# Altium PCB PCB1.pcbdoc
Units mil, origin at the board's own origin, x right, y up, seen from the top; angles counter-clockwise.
Board outline 1725 x 1680 mil, 2 copper layers (Top Layer, Bottom Layer); 21 components, 21 nets, 83 pads, 18 vias.
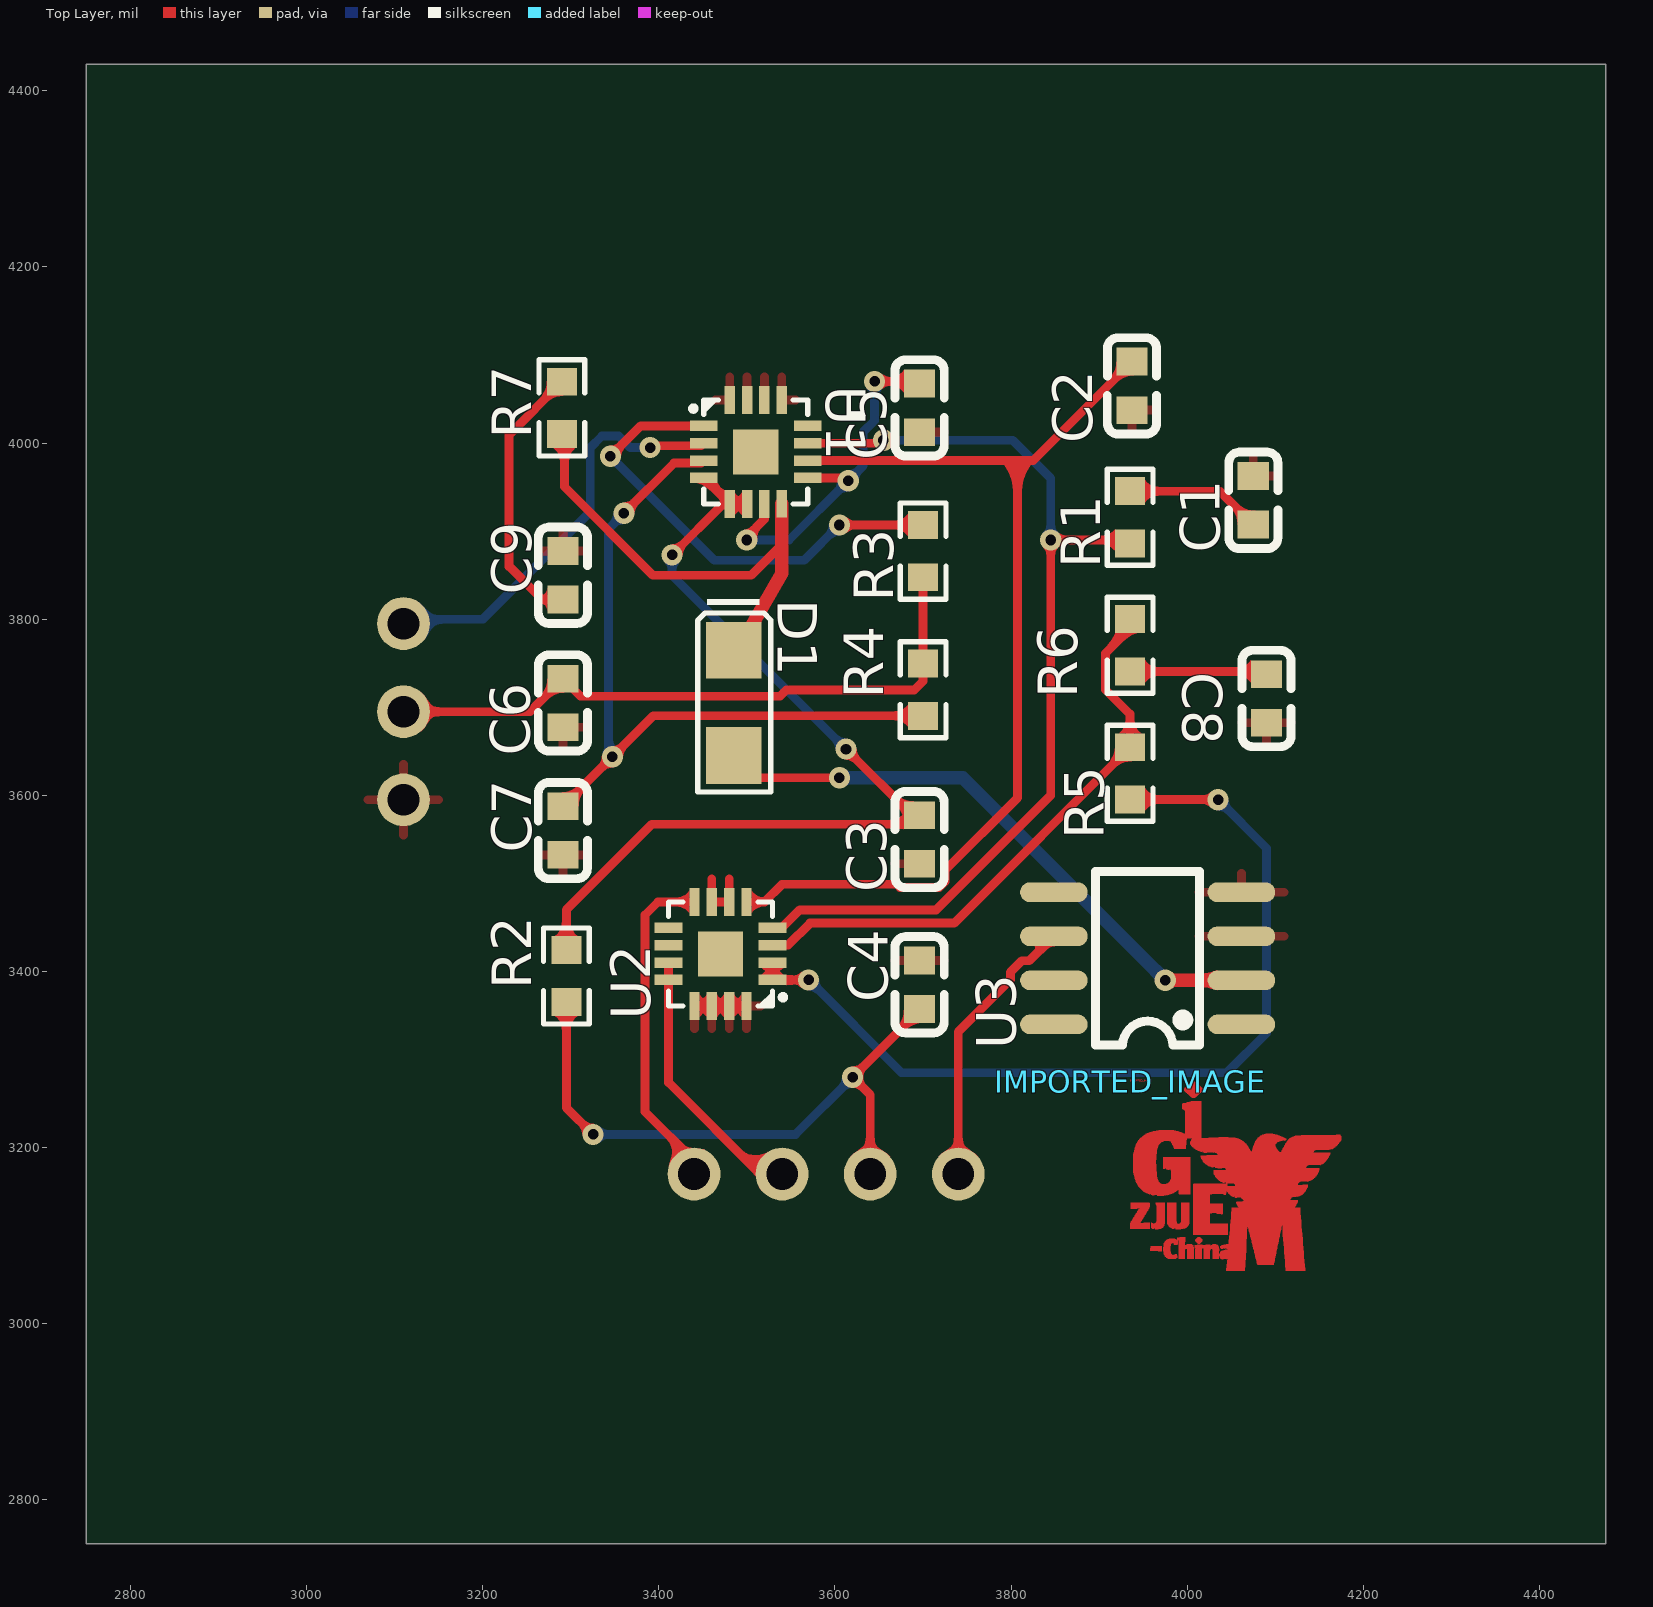
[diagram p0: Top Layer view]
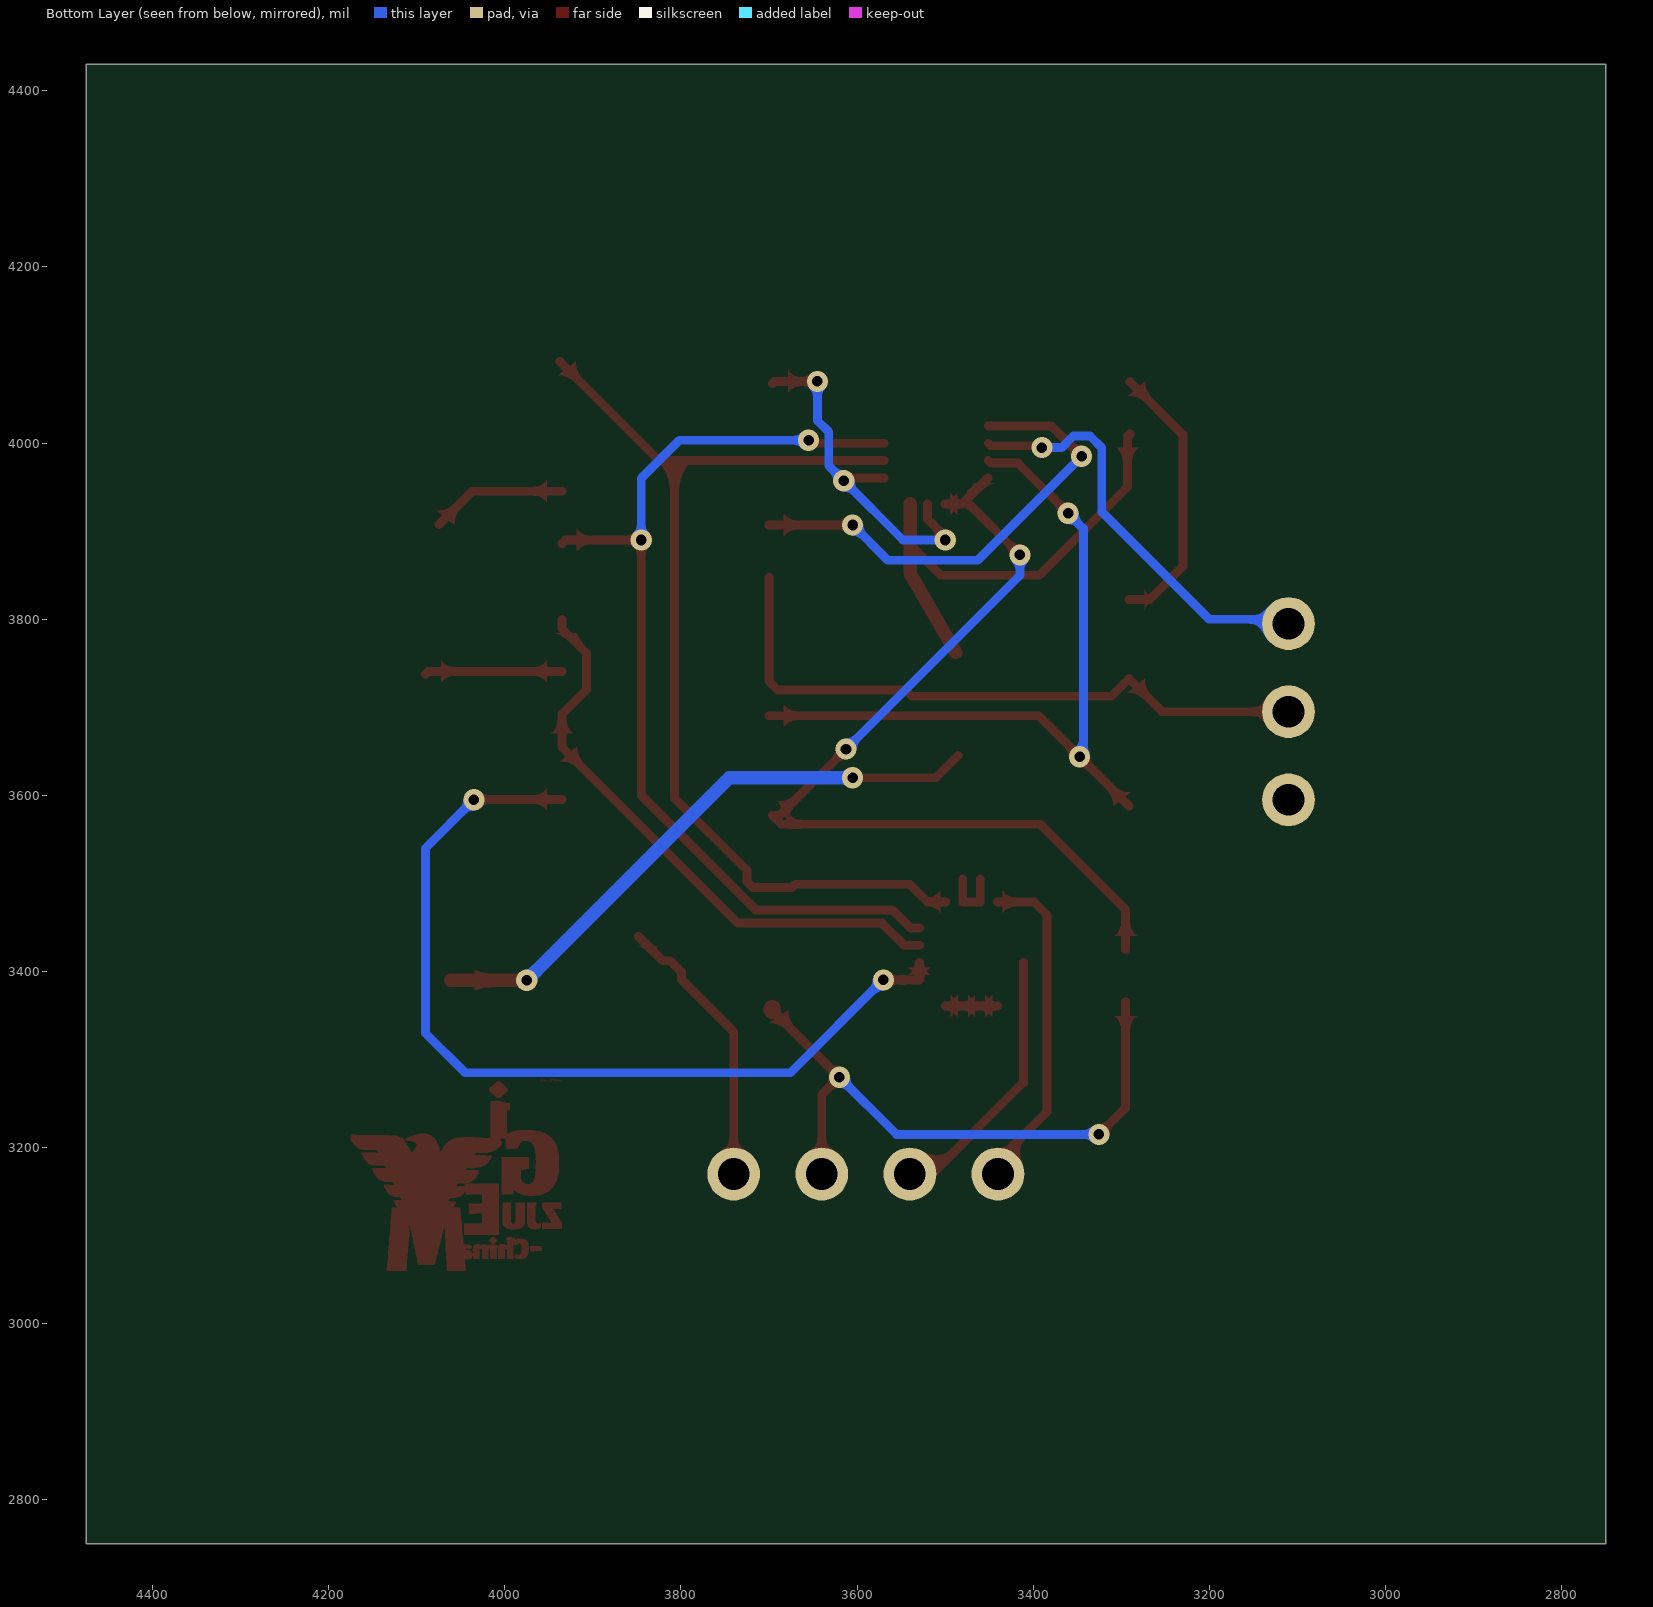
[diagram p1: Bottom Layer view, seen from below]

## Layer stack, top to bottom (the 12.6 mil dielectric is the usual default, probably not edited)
Top Layer: signal copper (thickness not stored)
Dielectric: dielectric 12.6, FR-4, Dk 4.8
Bottom Layer: signal copper (thickness not stored)

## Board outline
4475,2750 2750,2750 2750,4430 4475,4430

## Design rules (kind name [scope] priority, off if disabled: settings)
BoardOutlineClearance copperThickness1oz [All] p0: genericclearance=10 ignorepadtopadclearanceinfootprint=FALSE except(0: Arc-SplitContinuation Track-SplitContinuation SMDPad-SplitContinuation THPad-SplitContinuation Via-SplitContinuation Fill-SplitContinuation Poly-SplitContinuation Region-SplitContinuation Text-SplitContinuation; 6: Track-CutoutEdge SMDPad-CutoutEdge THPad-CutoutEdge Via-CutoutEdge Region-CutoutEdge; 11.8: Track-OutlineEdge SMDPad-OutlineEdge THPad-OutlineEdge Via-OutlineEdge Fill-OutlineEdge Region-OutlineEdge Poly-OutlineEdge Text-OutlineEdge Fill-CutoutEdge)
BoardOutlineClearance copperThickness2oz [All] p0: genericclearance=10 ignorepadtopadclearanceinfootprint=FALSE except(0: Arc-SplitContinuation Track-SplitContinuation SMDPad-SplitContinuation THPad-SplitContinuation Via-SplitContinuation Fill-SplitContinuation Poly-SplitContinuation Region-SplitContinuation Text-SplitContinuation; 6: Track-CutoutEdge SMDPad-CutoutEdge THPad-CutoutEdge Via-CutoutEdge Region-CutoutEdge; 11.8: Track-OutlineEdge SMDPad-OutlineEdge THPad-OutlineEdge Via-OutlineEdge Fill-OutlineEdge Region-OutlineEdge Poly-OutlineEdge Text-OutlineEdge Fill-CutoutEdge)
Clearance copperThickness1oz [(InNet('GND') OR InNet('$1N480') OR InNet('$1N501') OR InNet('$1N735') OR InNet('VP_HIGH') OR InNet('$1N663') OR InNet('VP_LOW') OR InNet('$1N1053') OR InNet('$1N1472') OR InNet('$1N1627') OR InNet('$1N1759') OR InNet('$1N2068') OR InNet('$1N382') OR InNet('$1N996') OR InNet('$1N1333') OR InNet('$1N1394') OR InNet('VSET') OR InNet('OUTPUT') OR InNet('3V_TO_12V') OR InNet('+5V') OR InNet('DATA_PATH'))] p1: gap=7 ignorepadtopadclearanceinfootprint=FALSE except(4: Track-Track; 6: Track-SMDPad SMDPad-SMDPad Track-THPad SMDPad-THPad THPad-THPad Track-Via SMDPad-Via THPad-Via Via-Via SMDPad-Fill THPad-Fill Via-Fill Fill-Fill Track-Region SMDPad-Region THPad-Region Via-Region Region-Region Track-Poly SMDPad-Poly THPad-Poly Via-Poly Fill-Poly Region-Poly Poly-Poly Track-Text SMDPad-Text THPad-Text Via-Text Fill-Text Region-Text Poly-Text Text-Text; 6.9: Track-Hole SMDPad-Hole THPad-Hole Via-Hole Fill-Hole Region-Hole Poly-Hole Text-Hole Sheet-Hole; 11.8: Track-Fill Fill-Region Track-Sheet SMDPad-Sheet THPad-Sheet Via-Sheet Fill-Sheet Region-Sheet Poly-Sheet Text-Sheet)
Clearance copperThickness2oz [All] p1: gap=7 ignorepadtopadclearanceinfootprint=FALSE except(6: Track-SMDPad SMDPad-SMDPad Track-THPad SMDPad-THPad THPad-THPad Track-Via SMDPad-Via THPad-Via Via-Via SMDPad-Fill THPad-Fill Via-Fill Fill-Fill Track-Region SMDPad-Region THPad-Region Via-Region Region-Region Track-Poly SMDPad-Poly THPad-Poly Via-Poly Fill-Poly Region-Poly Poly-Poly Track-Text SMDPad-Text THPad-Text Via-Text Fill-Text Region-Text Poly-Text Text-Text; 6.9: Track-Hole SMDPad-Hole THPad-Hole Via-Hole Fill-Hole Region-Hole Poly-Hole Text-Hole Sheet-Hole; 8: Track-Track; 11.8: Track-Fill Fill-Region Track-Sheet SMDPad-Sheet THPad-Sheet Via-Sheet Fill-Sheet Region-Sheet Poly-Sheet Text-Sheet)
DiffPairsRouting differentialPair [All] p1: maxuncoupledlength=10 minlimit=6 maxlimit=6 mostfreqgap=6 toplayer_minwidth=5 toplayer_prefwidth=10 toplayer_maxwidth=100 bottomlayer_minwidth=5 bottomlayer_prefwidth=10 bottomlayer_maxwidth=100
PasteMaskExpansion pasteMaskExpansion [All] p1: expansion=0
PlaneConnect innerPlane [All] p1: planeconnectstyle=Relief reliefexpansion=20 reliefentries=4 reliefconductorwidth=10 reliefairgap=10
PolygonConnect copperRegion [All] p1: connectstyle=Relief reliefentries=4 reliefconductorwidth=10 polygonreliefangle="90 Angle" airgapwidth=10
RoutingVias viaSize [All] p1: viastyle="Through Hole" holewidth=12.0078 minholewidth=11.811 maxholewidth=248.0314 width=24.0158 minwidth=19.685 maxwidth=393.7008
SolderMaskExpansion solderMaskExpansion [All] p1: useseparateexpansions=TRUE expansion=2 expansionbottom=2
Width copperThickness1oz [All] p1: maxlimit=100 minlimit=5 preferedwidth=10
Width copperThickness2oz [All] p1: maxlimit=100 minlimit=8 preferedwidth=10

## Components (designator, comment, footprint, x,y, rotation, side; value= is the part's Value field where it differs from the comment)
C1 "CAP_0603" C0603 4075,3935 r90 top
C2 "CAP_0603" C0603 3937.19,4065 r270 top
C3 "CAP_0603" C0603 3696.05,3549.84 r90 top
C4 "CAP_0603" C0603 3696.05,3385 r270 top
C5 "CAP_0603" C0603 3696.05,4040 r90 top
C6 "CAP_0603" C0603 3291.1,3705 r90 top
C7 "CAP_0603" C0603 3291.05,3560 r90 top
C8 "CAP_0603" C0603 4090,3710 r270 top
C9 "CAP_0603" C0603 3291.05,3850 r270 top
D1 "XYC-APD1206AC-L3" LED1206-RD 3485,3705 r270 top
IMPORTED_IMAGE "IMPORTED_IMAGE" IMPORTED_IMAGE 3935,3275 r0 top
R1 "Res_0603" R0603 3935,3915.7 r90 top
R2 "Res_0603" R0603 3295,3395 r270 top
R3 "Res_0603" R0603 3700,3877.35 r90 top
R4 "Res_0603" R0603 3700,3720 r270 top
R5 "Res_0603" R0603 3935,3625 r270 top
R6 "Res_0603" R0603 3935,3770.35 r90 top
R7 "Res_0603" R0603 3290,4040 r90 top
U1 "ADL5317ACPZ-REEL7" LFCSP-16_L3.0-W3.0-P0.50-BL-EP1.3-1 3510,3990 r270 top
U2 "AD8305ACPZ-RL7" LFCSP-16_L3.0-W3.0-P0.50-BL-EP1.3-1 3470,3420 r90 top
U3 "OPA380AIDR" SOIC-8_L5.0-W4.0-P1.27-LS6.0-BL 3955,3415 r90 top

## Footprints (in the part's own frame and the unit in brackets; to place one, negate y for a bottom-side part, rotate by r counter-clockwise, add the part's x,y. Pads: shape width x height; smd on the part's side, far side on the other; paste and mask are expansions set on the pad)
C0603 [mm]
  rect 0.8x0.9 smd: 1(-0.7,0) 2(0.7,0)
  silkscreen extent -1.39,-0.71 1.39,0.71
IMPORTED_IMAGE [mil]
  Top Layer region: 2417 vertices and 1 holes, not listed, extent 68.49,-215 240,-59.48
  Top Layer region: 65.25,-201.23 65.25,-201.04 65.25,-200.86 65.04,-200.86 64.84,-200.86 64.84,-200.19 64.84,-199.52 65.04,-199.52 65.25,-199.52 65.25,-194.89 65.25,-190.26 65.04,-190.26 64.84,-190.26 64.84,-190.08 64.84,-189.89 64.64,-189.89 64.43,-189.89 64.43,-189.71 64.43,-189.53 63.96,-189.53 63.49,-189.53 63.49,-189.71 63.49,-189.89 63.08,-189.89 62.67,-189.89 62.67,-190.08 62.67,-190.26 62.47,-190.26 62.27,-190.26 62.27,-195.56 62.27,-200.86 58.68,-200.86 55.09,-200.86 55.09,-190.44 55.09,-180.02 54.89,-180.02 54.69,-180.02 54.69,-179.84 54.69,-179.65 54.28,-179.65 53.87,-179.65 53.87,-178.62 53.87,-177.58 54.08,-177.58 54.28,-177.58 54.28,-177.4 54.28,-177.22 55.5,-177.22 56.72,-177.22 56.72,-177.03 56.72,-176.85 58.14,-176.85 59.56,-176.85 59.56,-176.67 59.56,-176.49 61.12,-176.49 62.67,-176.49 62.67,-179.17 62.67,-181.85 62.47,-181.85 62.27,-181.85 62.28,-184.32 62.3,-186.78 62.36,-186.57 62.42,-186.36 62.62,-186.36 62.81,-186.36 62.81,-186.17 62.81,-185.99 63.21,-185.99 63.62,-185.99 63.62,-185.81 63.62,-185.63 63.82,-185.63 64.03,-185.63 64.03,-185.44 64.03,-185.26 64.43,-185.26 64.84,-185.26 64.84,-185.08 64.84,-184.9 65.45,-184.9 66.06,-184.9 66.06,-184.71 66.06,-184.53 67.41,-184.53 68.76,-184.53 68.76,-184.71 68.76,-184.9 69.37,-184.9 69.98,-184.9 69.98,-185.08 69.98,-185.26 70.39,-185.26 70.8,-185.26 70.8,-185.44 70.8,-185.63 71,-185.63 71.2,-185.63 71.2,-185.81 71.2,-185.99 71.4,-185.99 71.61,-185.99 71.61,-186.36 71.61,-186.72 71.81,-186.72 72.01,-186.72 72.01,-187.27 72.01,-187.82 72.22,-187.82 72.42,-187.82 72.42,-194.52 72.42,-201.23 68.83,-201.23
  Top Layer region: 74.18,-201.23 74.18,-195.8 74.18,-190.38 74.38,-190.38 74.59,-190.38 74.59,-189.77 74.59,-189.16 74.18,-189.16 73.77,-189.16 73.77,-188.98 73.77,-188.8 73.57,-188.8 73.37,-188.8 73.37,-187.39 73.37,-185.99 73.98,-185.99 74.59,-185.99 74.59,-185.81 74.59,-185.63 75.4,-185.63 76.21,-185.63 76.21,-185.44 76.21,-185.26 78.98,-185.26 81.76,-185.26 81.76,-187.58 81.76,-189.89 81.56,-189.89 81.35,-189.89 81.35,-195.56 81.35,-201.23 77.77,-201.23
  Top Layer region: 225 vertices and 0 holes, not listed, extent 37.63,-201.23 54.15,-178.68
  Top Layer region: 100.85,-196.66 100.85,-201.23 97.26,-201.23 93.67,-201.23 93.67,-195.74 93.67,-190.26 93.47,-190.26 93.27,-190.26 93.27,-190.08 93.27,-189.89 92.39,-189.89 91.51,-189.89 91.51,-190.08 91.51,-190.26 91.3,-190.26 91.1,-190.26 91.1,-190.81 91.1,-191.35 90.9,-191.35 90.69,-191.35 90.69,-196.29 90.69,-201.23 87.11,-201.23 83.52,-201.23 83.52,-195.8 83.52,-190.38 83.72,-190.38 83.93,-190.38 83.93,-189.95 83.93,-189.53 83.72,-189.53 83.52,-189.53 83.52,-189.34 83.52,-189.16 83.32,-189.16 83.11,-189.16 83.11,-188.98 83.11,-188.8 82.91,-188.8 82.71,-188.8 82.71,-187.39 82.71,-185.99 83.52,-185.99 84.33,-185.99 84.33,-185.81 84.33,-185.63 85.14,-185.63 85.96,-185.63 85.96,-185.44 85.96,-185.26 88.53,-185.26 91.1,-185.26 91.1,-185.99 91.1,-186.72 91.37,-186.72 91.64,-186.72 91.64,-186.54 91.64,-186.36 91.84,-186.36 92.05,-186.36 92.05,-186.17 92.05,-185.99 92.25,-185.99 92.45,-185.99 92.45,-185.81 92.45,-185.63 92.86,-185.63 93.27,-185.63 93.27,-185.44 93.27,-185.26 93.67,-185.26 94.08,-185.26 94.08,-185.08 94.08,-184.9 95.84,-184.9 97.6,-184.9 97.6,-185.08 97.6,-185.26 98.21,-185.26 98.82,-185.26 98.82,-185.44 98.82,-185.63 99.02,-185.63 99.22,-185.63 99.22,-185.81 99.22,-185.99 99.42,-185.99 99.63,-185.99 99.63,-186.17 99.63,-186.36 99.83,-186.36 100.03,-186.36 100.03,-186.54 100.03,-186.72 100.24,-186.72 100.44,-186.72 100.44,-187.09 100.44,-187.45 100.64,-187.45 100.85,-187.45 100.85,-188.73 100.85,-190.01 101.05,-190.01 101.25,-190.01 101.25,-191.05 101.25,-192.09 101.05,-192.09 100.85,-192.09
  Top Layer region: 35.87,-189.77 35.87,-192.45 33.91,-192.45 31.95,-192.45 31.95,-192.27 31.95,-192.09 27.48,-192.09 23.01,-192.09 23.01,-190.68 23.01,-189.28 23.21,-189.28 23.42,-189.28 23.42,-188.19 23.42,-187.09 29.64,-187.09 35.87,-187.09
  Top Layer region: 78.92,-183.86 78.92,-184.04 78.17,-184.04 77.43,-184.04 77.43,-183.86 77.43,-183.68 77.22,-183.68 77.02,-183.68 77.02,-183.49 77.02,-183.31 76.82,-183.31 76.62,-183.31 76.62,-183.13 76.62,-182.95 76.41,-182.95 76.21,-182.95 76.21,-182.76 76.21,-182.58 76.01,-182.58 75.8,-182.58 75.8,-182.4 75.8,-182.21 75.6,-182.21 75.4,-182.21 75.4,-182.03 75.4,-181.85 75.19,-181.85 74.99,-181.85 74.99,-181.67 74.99,-181.48 74.79,-181.48 74.59,-181.48 74.59,-181.3 74.59,-181.12 74.38,-181.12 74.18,-181.12 74.18,-180.26 74.18,-179.41 74.38,-179.41 74.59,-179.41 74.59,-179.23 74.59,-179.04 74.79,-179.04 74.99,-179.04 74.99,-178.86 74.99,-178.68 75.19,-178.68 75.4,-178.68 75.4,-178.5 75.4,-178.31 75.6,-178.31 75.8,-178.31 75.8,-178.13 75.8,-177.95 76.01,-177.95 76.21,-177.95 76.21,-177.76 76.21,-177.58 76.41,-177.58 76.62,-177.58 76.62,-177.4 76.62,-177.22 76.82,-177.22 77.02,-177.22 77.02,-177.03 77.02,-176.85 78.17,-176.85 79.32,-176.85 79.32,-177.03 79.32,-177.22 79.53,-177.22 79.73,-177.22 79.73,-177.4 79.73,-177.58 79.93,-177.58 80.14,-177.58 80.14,-177.76 80.14,-177.95 80.34,-177.95 80.54,-177.95 80.54,-178.13 80.54,-178.31 80.74,-178.31 80.95,-178.31 80.95,-178.5 80.95,-178.68 81.15,-178.68 81.35,-178.68 81.35,-178.86 81.35,-179.04 81.56,-179.04 81.76,-179.04 81.76,-179.23 81.76,-179.41 81.96,-179.41 82.17,-179.41 82.17,-180.26 82.17,-181.12 81.96,-181.12 81.76,-181.12 81.76,-181.3 81.76,-181.48 81.56,-181.48 81.35,-181.48 81.35,-181.67 81.35,-181.85 81.15,-181.85 80.95,-181.85 80.95,-182.03 80.95,-182.21 80.74,-182.21 80.54,-182.21 80.54,-182.4 80.54,-182.58 80.34,-182.58 80.14,-182.58 80.14,-182.76 80.14,-182.95 79.93,-182.95 79.73,-182.95 79.73,-183.13 79.73,-183.31 79.53,-183.31 79.32,-183.31 79.32,-183.49 79.32,-183.68 79.12,-183.68 78.92,-183.68
  Top Layer region: 157 vertices and 0 holes, not listed, extent 42.5,-167.59 67.14,-137.73
  Top Layer region: 32.22,-167.41 32.22,-167.59 30.46,-167.59 28.7,-167.59 28.7,-167.41 28.7,-167.22 27.68,-167.22 26.67,-167.22 26.67,-167.04 26.67,-166.86 26.06,-166.86 25.45,-166.86 25.45,-166.67 25.45,-166.49 25.04,-166.49 24.64,-166.49 24.64,-166.31 24.64,-166.13 24.43,-166.13 24.23,-166.13 24.23,-163.26 24.23,-160.4 24.57,-160.4 24.91,-160.4 24.91,-160.58 24.91,-160.76 25.31,-160.76 25.72,-160.76 25.72,-160.95 25.72,-161.13 27.01,-161.13 28.29,-161.13 28.29,-160.95 28.29,-160.76 28.7,-160.76 29.1,-160.76 29.1,-160.58 29.1,-160.4 29.31,-160.4 29.51,-160.4 29.51,-160.21 29.51,-160.03 29.71,-160.03 29.92,-160.03 29.92,-159.48 29.92,-158.93 30.12,-158.93 30.32,-158.93 30.32,-149.73 30.32,-140.53 30.12,-140.53 29.92,-140.53 29.92,-140.16 29.92,-139.8 29.71,-139.8 29.51,-139.8 29.51,-139.43 29.51,-139.07 29.31,-139.07 29.1,-139.07 29.1,-138.4 29.1,-137.73 34.31,-137.73 39.53,-137.73 39.53,-149.55 39.53,-161.37 39.32,-161.37 39.12,-161.37 39.12,-162.1 39.12,-162.83 38.92,-162.83 38.71,-162.83 38.71,-163.2 38.71,-163.57 38.51,-163.57 38.31,-163.57 38.31,-163.93 38.31,-164.3 38.1,-164.3 37.9,-164.3 37.9,-164.66 37.9,-165.03 37.7,-165.03 37.5,-165.03 37.5,-165.21 37.5,-165.39 37.29,-165.39 37.09,-165.39 37.09,-165.58 37.09,-165.76 36.89,-165.76 36.68,-165.76 36.68,-165.94 36.68,-166.13 36.28,-166.13 35.87,-166.13 35.87,-166.31 35.87,-166.49 35.47,-166.49 35.06,-166.49 35.06,-166.67 35.06,-166.86 34.65,-166.86 34.25,-166.86 34.25,-167.04 34.25,-167.22 33.23,-167.22 32.22,-167.22
  Top Layer region: 253 vertices and 0 holes, not listed, extent 0,-166.86 22.47,-137.73
  Top Layer region: 829 vertices and 0 holes, not listed, extent 3.52,-129.56 80.95,-22.18
  Top Layer region: 361 vertices and 0 holes, not listed, extent 61.59,-18.4 82.57,0
LED1206-RD [mm]
  rect 1.635x1.6 smd: 1(-1.517,0) 2(1.517,0)
  silkscreen extent -2.99,-1.04 2.57,1.07
LFCSP-16_L3.0-W3.0-P0.50-BL-EP1.3-1 [mm]
  rect 0.3x0.8 smd: 1(-0.75,-1.5) 2(-0.25,-1.5) 3(0.25,-1.5) 4(0.75,-1.5) 9(0.75,1.5) 10(0.25,1.5) 11(-0.25,1.5) 12(-0.75,1.5)
  rect 0.8x0.3 smd: 5(1.5,-0.75) 6(1.5,-0.25) 7(1.5,0.25) 8(1.498,0.751) 13(-1.5,0.75) 14(-1.5,0.25) 15(-1.5,-0.25) 16(-1.5,-0.75)
  rect 1.3x1.3 smd: 17(0,0)
  silkscreen extent -1.5,-1.87 1.5,1.5
R0603 [mil]
  rect 31.75x34.02 smd: 1(-29.66,0) 2(29.66,0)
  silkscreen extent -55,-26 55,26
SOIC-8_L5.0-W4.0-P1.27-LS6.0-BL [mil]
  oval 22.38x76.78 smd: 1(-75,-106.5) 2(-25,-106.5) 3(25,-106.5) 4(75,-106.5) 5(75,106.5) 6(25,106.5) 7(-25,106.5) 8(-75,106.5)
  silkscreen extent -98,-59 98,59

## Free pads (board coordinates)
  round 60 hole 36: 1(3110,3595) 1(3110,3695) 1(3110,3795) 1(3440,3170) 1(3540,3170) 1(3640,3170) 1(3740,3170)

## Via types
v1: diameter 24.02, hole 12.01, Top Layer to Bottom Layer, 18 vias

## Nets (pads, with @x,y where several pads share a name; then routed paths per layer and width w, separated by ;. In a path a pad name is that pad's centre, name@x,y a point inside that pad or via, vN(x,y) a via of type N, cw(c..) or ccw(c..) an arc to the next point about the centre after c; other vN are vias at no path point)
3V_TO_12V: pad.1@3440,3170 U2.8 | length 379.7
  Top Layer w10: pad.1@3440,3170 3440,3185 3384.21,3240.79 3384.21,3464.21 3398.97,3478.97 U2.8
$1N382: R1.1 U1.11 U2.4 | length 1125.1
  Top Layer w10: U2.4 3539.53,3449.53 3560,3470 3715,3470 3845,3600 v1(3845,3890) 3931.04,3890 R1.1 ; U1.11 3651.69,3999.84 v1(3655,4003.16)
  Bottom Layer w10: v1(3655,4003.16) 3801.84,4003.16 3845,3960 v1(3845,3890)
$1N480: C1.1 R1.2 | length 155.7
  Top Layer w10: R1.2 4037.08,3945.36 C1.1
$1N501: C2.1 U1.10 U2.5 | length 1164.7
  Top Layer w10: U2.5 3520,3479.05 3540,3499.05 3670.28,3499.05 3673.79,3495.55 3718.32,3495.55 3724.75,3501.99 3724.75,3514.75 3807.32,3597.32 3807.32,3980.16 ; U1.10 3807.32,3980.16 ; C2.1 3824.8,3980.16 3807.32,3980.16
$1N663: C5.2 U1.7 U1.9 | length 416.8
  Top Layer w10: v1(3499.84,3890) 3499.84,3893.44 3519.84,3913.44 U1.7 ; U1.9 3611.7,3960.47 v1(3615,3957.17) ; v1(3645,4070) 3693.61,4070 C5.2
  Bottom Layer w10: v1(3499.84,3890) 3547.83,3890 v1(3615,3957.17) 3632.01,3974.18 3632.01,4012.68 3645,4025.67 v1(3645,4070)
$1N735: C3.2 R2.1 U1.4 U1.5 U1.6 | length 1058.8
  Top Layer w10: R2.1 3295,3470 3392.12,3567.12 3685.78,3567.12 C3.2 3687.6,3577.4 v1(3612.5,3652.5) ; v1(3415,3872.99) 3472.95,3930.95 U1.5 ; U1.4 U1.5 ; U1.6 U1.5
  Bottom Layer w10: v1(3415,3872.99) 3415,3850 v1(3612.5,3652.5)
$1N996: R3.2 U1.1 | length 540.7
  Top Layer w10: v1(3345,3985) 3379.53,4019.53 U1.1 ; v1(3605,3907.01) R3.2
  Bottom Layer w10: v1(3345,3985) 3462.99,3867.01 3565,3867.01 v1(3605,3907.01)
$1N1053: C7.2 R4.2 U1.3 | length 851.5
  Top Layer w10: C7.2 v1(3347.28,3643.79) 3393.83,3690.34 R4.2 ; v1(3360.34,3920.34) 3417.36,3977.36 3448.14,3977.36 U1.3
  Bottom Layer w10: v1@3347.93,3645 3342.93,3650 3342.93,3902.93 v1(3360.34,3920.34)
$1N1333: R5.2 U2.1 U2.2 | length 1030.9
  Top Layer w10: U2.2 U2.1 v1(3570,3390.47) ; R5.2 4034.66,3595.34 v1(4035,3595)
  Bottom Layer w10: v1(3570,3390.47) 3675.47,3285 4045,3285 4090,3330 4090,3540 v1(4035,3595)
$1N1394: R5.1 R6.2 U2.3 | length 667.6
  Top Layer w10: U2.3 3546.55,3429.84 3571.72,3455 3735.34,3455 R5.1 3935,3692.27 3907.01,3720.26 3907.01,3761.12 3935,3789.11 R6.2
$1N1472: C8.1 R6.1 | length 156.3
  Top Layer w10: R6.1 4086.87,3740.69 C8.1
$1N1627: C9.2 R7.2 | length 311.1
  Top Layer w10: R7.2 3230,4009.66 3230,3860 3267.56,3822.44 C9.2
$1N1759: D1.1 R7.1 U1.8 | length 546.5
  Top Layer w10: R7.1 3292.83,4007.51 3292.83,3950.34 3393.17,3850 3505,3850 3539.57,3884.57
  Top Layer w15: D1.1@3487.95,3762.09 3539.57,3852.09 3539.57,3884.57 U1.8
$1N2068: D1.2 U3.2 | length 682.2
  Top Layer w10: D1.2 3510.26,3620 v1(3605,3620)
  Top Layer w15: v1(3975,3390) U3.2
  Bottom Layer w15: v1(3605,3620) 3745,3620 v1(3975,3390)
+5V: U3.7
DATA_PATH: pad.1@3740,3170 U3.6 | length 320
  Top Layer w10: pad.1@3740,3170 3740,3331.5 3799.13,3390.63 3799.13,3399.18 3812.11,3412.17 3820.67,3412.17 U3.6
GND: C1.2 C2.2 C3.1 C4.1 C5.1 C6.1 C7.1 C8.2 C9.1 pad.1@3110,3595 U1.13 U1.14 U1.15 U1.16 U2.6 U2.7 U2.13 U2.14 U2.15 U2.16 U3.3 U3.4 | length 130.7
  Top Layer w10: U2.13 U2.14 U2.15 U2.16 ; 3460.16,3505 U2.7 U2.6 3480,3479.22 3480,3505
OUTPUT: pad.1@3540,3170 U2.11 U2.12 | length 308.3
  Top Layer w10: U2.11 U2.12 3410.95,3274.05 3515,3170 pad.1@3540,3170
VP_HIGH: C4.2 pad.1@3640,3170 R2.2 | length 711.7
  Top Layer w10: R2.2 3295,3245.34 v1(3325.34,3215) ; pad.1@3640,3170 3640,3260 v1(3620,3280) C4.2@3696.05,3356.05
  Top Layer w20: C4.2@3696.05,3356.05 C4.2
  Bottom Layer w10: v1(3325.34,3215) 3555,3215 v1(3620,3280)
VP_LOW: C6.2 pad.1@3110,3695 R3.1 R4.1 | length 739
  Top Layer w10: pad.1@3110,3695 3253.54,3695 C6.2 3311.1,3712.56 3537.56,3712.56 3544.63,3719.63 3689.97,3719.63 3700,3729.66 R4.1 R3.1
VSET: pad.1@3110,3795 U1.2 | length 477.2
  Top Layer w10: v1(3390,3994.84) 3392.22,3997.05 3448.16,3997.05 U1.2
  Bottom Layer w10: pad.1@3110,3800 3200.16,3800 3322.01,3921.84 3322.01,3994.52 3335.48,4007.99 3354.52,4007.99 3367.68,3994.84 v1(3390,3994.84)
pads on no net: U1.12 U1.17 U2.9 U2.10 U2.17 U3.1 U3.5 U3.8

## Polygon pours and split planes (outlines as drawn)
GND on Top Layer (solid, remove dead copper, pour order 0): 3000,4180 4225,4180 4225,3000 3000,3000

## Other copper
Top Layer:
  region net VP_HIGH: 3635,3210.84 3645,3210.84 3645.1,3208.54 3645.39,3206.55 3645.87,3204.84 3646.5,3203.38 3647.3,3202.11 3648.23,3201 3650.47,3199.1 3656.07,3195.45 3659.24,3193.05 3660.86,3191.57 3662.5,3189.84 3617.5,3189.84 3619.14,3191.57 3620.76,3193.05 3623.93,3195.45 3629.53,3199.1 3631.77,3201 3632.7,3202.11 3633.5,3203.38 3634.13,3204.84 3634.61,3206.55 3634.9,3208.54
  region net VP_LOW: 3150.84,3700 3150.84,3690 3148.54,3689.9 3146.55,3689.61 3144.84,3689.13 3143.38,3688.5 3142.11,3687.7 3141,3686.77 3139.1,3684.53 3135.45,3678.93 3133.05,3675.76 3131.57,3674.14 3129.84,3672.5 3129.84,3717.5 3131.57,3715.86 3133.05,3714.24 3135.45,3711.07 3139.1,3705.47 3141,3703.23 3142.11,3702.3 3143.38,3701.5 3144.84,3700.87 3146.55,3700.39 3148.54,3700.1
  region net DATA_PATH: 3735,3210.84 3745,3210.84 3745.1,3208.54 3745.39,3206.55 3745.87,3204.84 3746.5,3203.38 3747.3,3202.11 3748.23,3201 3750.47,3199.1 3756.07,3195.45 3759.24,3193.05 3760.86,3191.57 3762.5,3189.84 3717.5,3189.84 3719.14,3191.57 3720.76,3193.05 3723.93,3195.45 3729.53,3199.1 3731.77,3201 3732.7,3202.11 3733.5,3203.38 3734.13,3204.84 3734.61,3206.55 3734.9,3208.54
  region net OUTPUT: 3507.15,3170.78 3495.47,3196.6 3496.85,3195.38 3498.35,3194.33 3499.96,3193.45 3501.68,3192.72 3503.47,3192.16 3505.33,3191.74 3507.24,3191.48 3509.17,3191.37 3513.08,3191.56 3516.92,3192.3 3520.56,3193.55 3522.27,3194.37 3523.87,3195.3 3516.92,3150.84 3515.72,3152.38 3514.78,3153.83 3513.5,3156.45 3512.78,3158.83 3512.32,3161.07 3511.82,3163.27 3510.99,3165.55 3509.54,3168.02 3508.48,3169.35
  region net $1N480: 4051.98,3923.39 4061.02,3928.49 ccw(c4076.93,3949.7) 4076.93,3923.19 4057.28,3907.48 ccw(c4030.77,3907.48)
  region net $1N501: 3923.21,4071.51 3914.17,4076.61 ccw(c3892.96,4092.52) 3919.48,4092.52 3939.12,4076.81 ccw(c3939.12,4050.3)
  region net $1N735: 3663.34,3562.12 3663.34,3572.12 ccw(c3663.34,3590.87) 3678.34,3579.62 3678.34,3561.66 ccw(c3663.34,3322.38)
  region net $1N735: 3673.03,3584.89 3673.62,3598.45 ccw(c3689.53,3619.67) 3689.53,3593.15 3678.34,3568.98 ccw(c3651.82,3568.98)
  region net VP_HIGH: 3683.46,3336.39 3673.03,3340.1 ccw(c3651.82,3356.01) 3678.33,3356.01 3699.37,3341.69 ccw(c3699.37,3315.18)
  region net $1N663: 3663.34,4065 3663.34,4075 ccw(c3663.34,4093.75) 3678.34,4082.5 3678.34,4057.5 ccw(c3663.34,4046.25)
  region net VP_LOW: 3277.12,3711.51 3268.08,3716.61 ccw(c3246.87,3732.52) 3273.38,3732.52 3293.03,3716.81 ccw(c3293.03,3690.3)
  region net $1N1053: 3305.03,3608.61 3314.07,3603.51 ccw(c3335.29,3587.6) 3308.77,3587.6 3289.12,3603.31 ccw(c3289.12,3629.82)
  region net $1N1472: 4057.28,3735.69 4057.28,3745.69 ccw(c4057.28,3764.44) 4072.28,3753.19 4072.28,3728.19 ccw(c4057.28,3716.94)
  region net $1N1627: 3267.56,3817.44 3267.56,3827.44 ccw(c3265.58,3834.94) 3273.33,3834.94 3273.33,3809.94 ccw(c3265.58,3809.94)
  region net $1N480: 3967.01,3950.36 3967.01,3940.36 ccw(c3967.01,3921.61) 3952.01,3932.86 3952.01,3957.86 ccw(c3967.01,3969.11)
  region net $1N382: 3902.99,3885 3902.99,3895 ccw(c3902.99,3914.72) 3917.99,3901.92 3917.99,3877.5 ccw(c3902.99,3866.25)
  region net VP_HIGH: 3300,3334.46 3290,3334.46 ccw(c3271.25,3334.46) 3282.5,3349.46 3307.5,3349.46 ccw(c3318.75,3334.46)
  region net $1N735: 3290,3455.54 3300,3455.54 ccw(c3318.75,3455.54) 3307.5,3440.54 3282.5,3440.54 ccw(c3271.25,3455.54)
  region net $1N996: 3667.99,3902.01 3667.99,3912.01 ccw(c3667.99,3930.76) 3682.99,3919.51 3682.99,3894.51 ccw(c3667.99,3883.26)
  region net $1N1053: 3667.99,3685.34 3667.99,3695.34 ccw(c3667.99,3714.09) 3682.99,3702.84 3682.99,3677.84 ccw(c3667.99,3666.59)
  region net $1N1333: 3967.01,3600.34 3967.01,3590.34 ccw(c3967.01,3571.59) 3952.01,3582.84 3952.01,3607.84 ccw(c3967.01,3619.09)
  region net $1N1394: 3920.89,3633.48 3912.69,3639.42 ccw(c3891.48,3655.33) 3917.99,3655.33 3936.8,3638.78 ccw(c3936.8,3612.27)
  region net $1N1394: 3930,3685.54 3940,3685.54 ccw(c3958.75,3685.54) 3947.5,3670.54 3922.5,3670.54 ccw(c3911.25,3685.54)
  region net $1N1394: 3929.21,3776.24 3909.87,3771.05 ccw(c3885.96,3794.95) 3917.99,3784.13 3942.53,3784.13 ccw(c3951.29,3754.16)
  region net $1N1472: 3967.01,3745.69 3967.01,3735.69 ccw(c3967.01,3716.94) 3952.01,3728.19 3952.01,3753.19 ccw(c3967.01,3764.44)
  region net $1N1627: 3275.89,4048.48 3267.69,4054.42 ccw(c3246.48,4070.33) 3272.99,4070.33 3291.8,4053.78 ccw(c3291.8,4027.27)
  region net $1N1759: 3297.83,3979.46 3287.83,3979.46 ccw(c3269.08,3979.46) 3280.33,3994.46 3305.33,3994.46 ccw(c3316.58,3979.46)
  region net $1N735: 3480.47,3925.95 3480.47,3935.95 ccw(c3480.47,3952.36) 3494.26,3943.45 3494.26,3918.45 ccw(c3480.47,3909.53)
  region net $1N735: 3500.16,3935.95 3500.16,3925.95 ccw(c3500.16,3909.53) 3486.38,3918.45 3486.38,3943.45 ccw(c3500.16,3952.36)
  region net $1N735: 3466.68,3937.67 3462.58,3955.91 ccw(c3503.86,3997.19) 3474.57,3946.69 3474.57,3924.35 ccw(c3444.6,3915.59)
  region net $1N735: 3475.91,3942.58 3457.67,3946.68 ccw(c3435.59,3924.6) 3444.35,3954.57 3466.69,3954.57 ccw(c3517.19,3983.86)
  region net GND: 3479.84,3355.95 3479.84,3365.95 ccw(c3479.84,3382.36) 3493.62,3373.45 3493.62,3348.45 ccw(c3479.84,3339.53)
  region net GND: 3460.16,3355.95 3460.16,3365.95 ccw(c3460.16,3382.34) 3473.93,3373.45 3473.93,3348.45 ccw(c3460.16,3339.55)
  region net GND: 3499.53,3365.95 3499.53,3355.95 ccw(c3499.53,3339.53) 3485.74,3348.45 3485.74,3373.45 ccw(c3499.53,3382.36)
  region net GND: 3479.84,3365.95 3479.84,3355.95 ccw(c3479.84,3339.55) 3466.06,3348.45 3466.06,3373.45 ccw(c3479.84,3382.34)
  region net GND: 3440.47,3355.95 3440.47,3365.95 ccw(c3440.47,3382.36) 3454.25,3373.45 3454.25,3348.45 ccw(c3440.47,3339.53)
  region net GND: 3460.16,3365.95 3460.16,3355.95 ccw(c3460.16,3339.53) 3446.37,3348.45 3446.37,3373.45 ccw(c3460.16,3382.36)
  region net 3V_TO_12V: 3419.53,3473.97 3419.53,3483.97 ccw(c3419.53,3502.72) 3434.53,3491.47 3434.53,3466.47 ccw(c3419.53,3455.22)
  region net $1N501: 3520,3484.05 3520,3474.05 ccw(c3520,3456.15) 3505.43,3466.55 3505.43,3491.55 ccw(c3520,3501.96)
  region net $1N1333: 3534.05,3390.47 3524.05,3390.47 ccw(c3507.62,3390.47) 3516.55,3404.26 3541.55,3404.26 ccw(c3550.49,3390.47)
  region net $1N1333: 3524.05,3410.16 3534.05,3410.16 ccw(c3550.49,3410.16) 3541.55,3396.37 3516.55,3396.37 ccw(c3507.62,3410.16)
  region net $1N1333: 3559.8,3395.47 3559.8,3385.47 ccw(c3559.8,3260.7) 3544.8,3384.56 3544.8,3396.37 ccw(c3559.8,3520.23)
  region net $1N2068: 4011.8,3382.5 4011.8,3397.5 4015.95,3397.66 4019.92,3398.08 4023.6,3398.67 4026.89,3399.34 4031.94,3400.61 4034.3,3401.19 4034.3,3378.81 4031.94,3379.39 4026.89,3380.66 4023.6,3381.33 4019.92,3381.92 4015.95,3382.34
  region net DATA_PATH: 3836.49,3420.92 3817.14,3415.71 3821.67,3420.02 3823.93,3422.21 3825.83,3424.27 3827.13,3426.08 3827.48,3426.85 3827.57,3427.52 3827.38,3428.06 3826.88,3428.47 3826.03,3428.72 3824.81,3428.81 3849.81,3428.81 3847.8,3428.63 3845.93,3428.13 3844.18,3427.35 3842.54,3426.34 3840.97,3425.15 3839.45,3423.82
  region net 3V_TO_12V: 3410.37,3207.56 3428.69,3203.38 3429.89,3202.33 3431.16,3201.49 3432.49,3200.83 3433.88,3200.32 3436.79,3199.69 3439.84,3199.39 3446.14,3198.94 3449.28,3198.39 3450.82,3197.94 3452.34,3197.34 3411.33,3178.83 3413.66,3186.69 3414.53,3190.51 3415.02,3194.23 3415.07,3196.04 3414.98,3197.82 3414.73,3199.56 3414.29,3201.25 3413.65,3202.9 3412.8,3204.51 3411.71,3206.06
  region net $1N2068: 3991.35,3397.5 3991.35,3382.5 3988.97,3382.58 3986.83,3382.58 3985.82,3382.44 3984.84,3382.16 3983.89,3381.69 3982.94,3380.99 3982.94,3399.01 3983.89,3398.31 3984.84,3397.84 3985.82,3397.56 3986.83,3397.42 3988.97,3397.42
  region net $1N382: 3850,3873.65 3840,3873.65 3839.91,3874.79 3839.66,3875.92 3838.75,3878.14 3837.47,3880.21 3835.99,3882.06 3854.01,3882.06 3852.53,3880.21 3851.25,3878.14 3850.34,3875.92 3850.09,3874.79
  region net $1N382: 3861.35,3895 3861.35,3885 3860.21,3884.91 3859.08,3884.66 3856.86,3883.75 3854.79,3882.47 3852.94,3880.99 3852.94,3899.01 3854.79,3897.53 3856.86,3896.25 3859.08,3895.34 3860.21,3895.09
  region net $1N663: 3661.35,4075 3661.35,4065 3660.21,4064.91 3659.08,4064.66 3656.86,4063.75 3654.79,4062.47 3652.94,4060.99 3652.94,4079.01 3654.79,4077.53 3656.86,4076.25 3659.08,4075.34 3660.21,4075.09
  region net $1N735: 3627.6,3644.48 3620.52,3637.4 3619.66,3638.15 3618.67,3638.77 3616.47,3639.69 3614.09,3640.25 3611.75,3640.52 3624.48,3653.25 3624.75,3650.91 3625.31,3648.53 3626.23,3646.33 3626.85,3645.34
  region net $1N735: 3423.02,3888.09 3430.1,3881.02 3429.35,3880.15 3428.73,3879.17 3427.81,3876.96 3427.25,3874.59 3426.98,3872.24 3414.25,3884.98 3416.59,3885.24 3418.97,3885.8 3421.17,3886.72 3422.16,3887.35
  region net $1N663: 3504.74,3905.41 3514.39,3900.92 3513.67,3900.05 3513.06,3899.01 3512.14,3896.61 3511.69,3894.06 3511.73,3891.69 3496.68,3901.58 3498.87,3902.22 3501.01,3902.99 3502.99,3904.02
  region net $1N996: 3621.35,3912.01 3621.35,3902.01 3620.21,3901.92 3619.08,3901.66 3616.86,3900.76 3614.79,3899.47 3612.94,3898 3612.94,3916.01 3614.79,3914.54 3616.86,3913.26 3619.08,3912.35 3620.21,3912.1
  region net $1N996: 3353.02,4000.1 3360.1,3993.02 3359.35,3992.16 3358.73,3991.17 3357.81,3988.97 3357.25,3986.59 3356.98,3984.25 3344.25,3996.98 3346.59,3997.25 3348.97,3997.81 3351.17,3998.73 3352.16,3999.35
  region net $1N1053: 3368.37,3935.44 3375.44,3928.37 3374.7,3927.5 3374.08,3926.52 3373.15,3924.31 3372.59,3921.94 3372.33,3919.59 3359.59,3932.33 3361.94,3932.59 3364.31,3933.15 3366.52,3934.08 3367.5,3934.7
  region net $1N1053: 3339.26,3628.69 3332.19,3635.77 3332.93,3636.63 3333.55,3637.61 3334.48,3639.82 3335.03,3642.2 3335.3,3644.54 3348.04,3631.81 3345.69,3631.54 3343.32,3630.98 3341.11,3630.06 3340.13,3629.43
  region net $1N1053: 3355.31,3658.88 3362.38,3651.81 3361.64,3650.95 3361.02,3649.96 3360.09,3647.76 3359.53,3645.38 3359.27,3643.04 3346.53,3655.77 3348.88,3656.04 3351.25,3656.6 3353.46,3657.52 3354.44,3658.14
  region net VP_HIGH: 3310.24,3223.02 3317.32,3230.1 3318.18,3229.35 3319.17,3228.73 3321.37,3227.81 3323.75,3227.25 3326.09,3226.98 3313.36,3214.25 3313.09,3216.59 3312.53,3218.97 3311.61,3221.17 3310.99,3222.16
  region net VP_HIGH: 3635.1,3271.98 3628.02,3264.9 3627.16,3265.65 3626.17,3266.27 3623.97,3267.19 3621.59,3267.75 3619.25,3268.02 3631.98,3280.75 3632.25,3278.41 3632.81,3276.03 3633.73,3273.83 3634.35,3272.84
  region net VP_HIGH: 3628.02,3295.1 3635.1,3288.02 3634.35,3287.16 3633.73,3286.17 3632.81,3283.97 3632.25,3281.59 3631.98,3279.25 3619.25,3291.98 3621.59,3292.25 3623.97,3292.81 3626.17,3293.73 3627.16,3294.35
  region net $1N1333: 3553.65,3385.47 3553.65,3395.47 3554.79,3395.55 3555.92,3395.81 3558.14,3396.72 3560.21,3398 3562.06,3399.47 3562.06,3381.46 3560.21,3382.93 3558.14,3384.21 3555.92,3385.12 3554.79,3385.38
  region net $1N1333: 4018.4,3590.34 4018.91,3600.34 4020.05,3600.43 4021.18,3600.67 4023.38,3601.55 4025.44,3602.8 4027.32,3604.23 4026.81,3586.22 4024.99,3587.73 4022.91,3589.05 4020.68,3589.99 4019.54,3590.25
  region net $1N501: 3802.32,3945.16 ccw(c3752.32,3945.16) 3792.32,3975.16 3807.32,3980.16 3822.32,3975.16 ccw(c3862.32,3945.16) 3812.32,3945.16
Bottom Layer:
  region net VSET: 3146.82,3805 3154.32,3795 3152.16,3794.89 3150.24,3794.58 3148.52,3794.07 3146.99,3793.38 3145.6,3792.52 3144.35,3791.52 3143.2,3790.37 3142.13,3789.1 3140.12,3786.24 3138.11,3783.05 3135.91,3779.64 3133.32,3776.12 3125.82,3820.49 3128.21,3818.71 3130.7,3816.44 3135.9,3811.29 3138.59,3808.88 3141.31,3806.88 3142.68,3806.1 3144.06,3805.51 3145.44,3805.13
  region net $1N2068: 3958.14,3396.26 3968.74,3406.86 3970.37,3405.13 3971.88,3403.61 3972.69,3403 3973.58,3402.5 3974.59,3402.16 3975.75,3401.98 3963.02,3389.25 3962.84,3390.41 3962.5,3391.42 3962,3392.31 3961.39,3393.12 3959.87,3394.63
  region net $1N2068: 3621.35,3627.5 3621.35,3612.5 3618.97,3612.58 3616.83,3612.58 3615.82,3612.44 3614.84,3612.16 3613.89,3611.69 3612.94,3610.99 3612.94,3629.01 3613.89,3628.31 3614.84,3627.84 3615.82,3627.56 3616.83,3627.42 3618.97,3627.42
  region net $1N382: 3840,3906.35 3850,3906.35 3850.09,3905.21 3850.34,3904.08 3851.25,3901.86 3852.53,3899.79 3854.01,3897.94 3835.99,3897.94 3837.47,3899.79 3838.75,3901.86 3839.66,3904.08 3839.91,3905.21
  region net $1N663: 3650,4053.65 3640,4053.65 3639.91,4054.79 3639.66,4055.92 3638.75,4058.14 3637.47,4060.21 3635.99,4062.06 3654.01,4062.06 3652.53,4060.21 3651.25,4058.14 3650.34,4055.92 3650.09,4054.79
  region net $1N663: 3606.98,3942.08 3599.9,3949.15 3600.65,3950.02 3601.27,3951 3602.19,3953.21 3602.75,3955.58 3603.02,3957.92 3615.75,3945.19 3613.41,3944.92 3611.03,3944.36 3608.83,3943.44 3607.84,3942.82
  region net $1N663: 3623.02,3972.27 3630.1,3965.2 3629.35,3964.33 3628.73,3963.35 3627.81,3961.14 3627.25,3958.77 3626.98,3956.42 3614.25,3969.16 3616.59,3969.42 3618.97,3969.98 3621.17,3970.91 3622.16,3971.53
  region net $1N382: 3671.35,4008.16 3671.35,3998.16 3670.21,3998.07 3669.08,3997.81 3666.86,3996.91 3664.79,3995.62 3662.94,3994.15 3662.94,4012.16 3664.79,4010.69 3666.86,4009.41 3669.08,4008.5 3670.21,4008.25
  region net $1N735: 3597.4,3660.52 3604.48,3667.6 3605.34,3666.85 3606.33,3666.23 3608.53,3665.31 3610.91,3664.75 3613.25,3664.48 3600.52,3651.75 3600.25,3654.09 3599.69,3656.47 3598.77,3658.67 3598.15,3659.66
  region net $1N735: 3420,3856.64 3410,3856.64 3409.91,3857.78 3409.66,3858.92 3408.75,3861.13 3407.47,3863.2 3405.99,3865.05 3424.01,3865.05 3422.53,3863.2 3421.25,3861.13 3420.34,3858.92 3420.09,3857.78
  region net $1N996: 3596.98,3891.91 3589.9,3898.98 3590.65,3899.85 3591.27,3900.83 3592.19,3903.04 3592.75,3905.41 3593.02,3907.76 3605.75,3895.02 3603.41,3894.76 3601.03,3894.2 3598.83,3893.27 3597.84,3892.65
  region net $1N1053: 3352.32,3905.25 3345.25,3912.32 3345.99,3913.19 3346.61,3914.17 3347.54,3916.38 3348.09,3918.75 3348.36,3921.1 3361.1,3908.36 3358.75,3908.09 3356.38,3907.54 3354.17,3906.61 3353.19,3905.99
  region net $1N1053: 3337.93,3656.33 3347.93,3662.86 3348.03,3661.71 3348.32,3660.5 3349.38,3658.06 3350.11,3656.93 3350.93,3655.93 3351.84,3655.09 3352.8,3654.46 3336.01,3647.93 3337.33,3652.06 3337.76,3654.21
  region net VP_HIGH: 3341.69,3220 3341.69,3210 3340.55,3209.91 3339.42,3209.66 3337.2,3208.75 3335.13,3207.47 3333.28,3205.99 3333.28,3224.01 3335.13,3222.53 3337.2,3221.25 3339.42,3220.34 3340.55,3220.09
  region net VP_HIGH: 3611.98,3264.9 3604.9,3271.98 3605.65,3272.84 3606.27,3273.83 3607.19,3276.03 3607.75,3278.41 3608.02,3280.75 3620.75,3268.02 3618.41,3267.75 3616.03,3267.19 3613.83,3266.27 3612.84,3265.65
  region net $1N1333: 3585.1,3382.44 3578.02,3375.37 3577.16,3376.11 3576.17,3376.73 3573.97,3377.66 3571.59,3378.22 3569.25,3378.48 3581.98,3391.22 3582.25,3388.87 3582.81,3386.5 3583.73,3384.29 3584.35,3383.31
  region net $1N1333: 4050.1,3586.98 4043.02,3579.9 4042.16,3580.65 4041.17,3581.27 4038.97,3582.19 4036.59,3582.75 4034.25,3583.02 4046.98,3595.75 4047.25,3593.41 4047.81,3591.03 4048.73,3588.83 4049.35,3587.84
